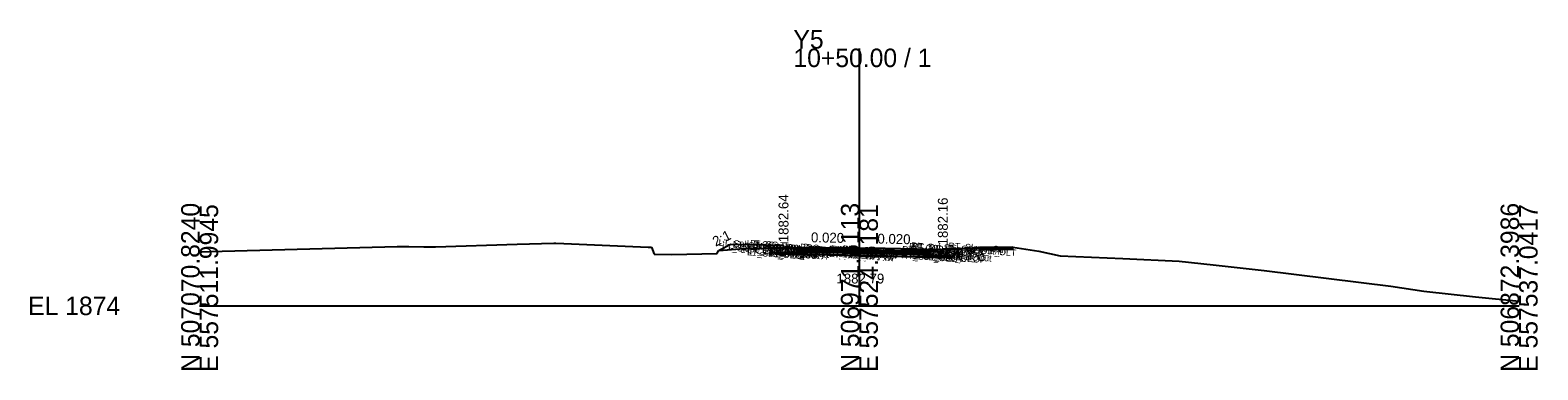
# Model space of a CAD drawing. Extents: x -26 to 1503, y -10 to 2043.
# Drawn here: x -25.7 to 202.8, y 490.3 to 541.8 of the extents above; entities that cross this region are included whole.
import ezdxf

# ---------------------------------------------------------------- set-up
doc = ezdxf.new("R2010")
doc.units = 0
for name, color, linetype in [('Default', 7, 'Continuous'), ('Exist Cross Section Cell', 7, 'Continuous'), ('Exist XS Center Line Elevation Label', 7, 'Continuous'), ('Exist XS Ground Line', 7, 'Continuous'), ('Prop CMT Conc Surface', 7, 'Continuous'), ('Prop CMT Concrete Structures', 7, 'Continuous'), ('Prop CMT Pvmt Course 1', 7, 'Continuous'), ('Prop CMT Pvmt Course 1 CG', 7, 'Continuous'), ('Prop CMT Pvmt Course 2', 7, 'Continuous'), ('Prop CMT Pvmt Course 3', 7, 'Continuous'), ('Prop CMT Pvmt Surface', 7, 'Continuous'), ('Prop CMT Slope Grass', 7, 'Continuous'), ('Prop CMT Subgrade Earthwork', 7, 'Continuous'), ('Prop XS Earthwork Shape', 7, 'Continuous'), ('Prop XS Hydro Elevations', 7, 'Continuous'), ('Prop XS SE Text', 7, 'Continuous'), ('Prop XS Side Slope Text', 7, 'Continuous'), ('Typical Text Asphalt at Bridge Approach CELL', 7, 'Continuous')]:
    doc.layers.add(name, color=color, linetype=linetype)

msp = doc.modelspace()

# ---------------------------------------------------------------- linework, layer by layer
at = {"layer": 'Exist Cross Section Cell'}
for p, q in [((100, 500), (100, 538.98)), ((0, 500), (100, 500)), ((100, 500), (200, 500))]:
    msp.add_line(p, q, dxfattribs=at)
at = {"layer": 'Exist XS Ground Line'}
for p, q in [((0, 508.17), (0.32, 508.19)), ((0.32, 508.19), (1.55, 508.22)), ((1.55, 508.22), (29.94, 508.98)), ((29.94, 508.98), (31.72, 509)), ((31.72, 509), (33.96, 508.97)), ((33.96, 508.97), (35.04, 508.96)), ((35.04, 508.96), (35.77, 508.97)), ((35.77, 508.97), (48.11, 509.35)), ((48.11, 509.35), (53.69, 509.5)), ((53.69, 509.5), (53.99, 509.48)), ((53.99, 509.48), (55.21, 509.43)), ((55.21, 509.43), (67.97, 508.91)), ((67.97, 508.91), (68.49, 508.91)), ((68.49, 508.91), (68.91, 507.84)), ((68.91, 507.84), (71.52, 507.8)), ((71.52, 507.8), (78.43, 507.93)), ((78.43, 507.93), (78.63, 508.4)), ((78.63, 508.4), (81.89, 508.65)), ((81.89, 508.65), (90.53, 508.85)), ((90.53, 508.85), (94.84, 508.82)), ((94.84, 508.82), (99.36, 508.81)), ((99.36, 508.81), (100, 508.79)), ((100, 508.79), (103.93, 508.72)), ((103.93, 508.72), (108.62, 508.64)), ((108.62, 508.64), (113.17, 508.49)), ((113.17, 508.49), (113.63, 508.5)), ((113.63, 508.5), (118.28, 508.87)), ((118.28, 508.87), (120.69, 508.9)), ((120.69, 508.9), (123.26, 508.92)), ((123.26, 508.92), (127.2, 508.27)), ((127.2, 508.27), (130.42, 507.59)), ((130.42, 507.59), (139.92, 507.16)), ((139.92, 507.16), (148.47, 506.76)), ((148.47, 506.76), (153.63, 506.21)), ((153.63, 506.21), (161.37, 505.34)), ((161.37, 505.34), (180.58, 502.98)), ((180.58, 502.98), (185.58, 502.24)), ((185.58, 502.24), (193.37, 501.36)), ((193.37, 501.36), (200, 500.71))]:
    msp.add_line(p, q, dxfattribs=at)
at = {"layer": 'Prop CMT Conc Surface'}
for points in [[(88.5, 508.64), (88.5, 509.14), (88, 509.14)], [(90.5, 508.68), (88.5, 508.64)], [(110.65, 508.28), (112.65, 508.16)], [(112.65, 508.16), (112.65, 508.66), (113.15, 508.66)], [(118.27, 508.81), (123.27, 508.91)]]:
    msp.add_lwpolyline(points, dxfattribs=at)
at = {"layer": 'Prop CMT Concrete Structures'}
for points in [[(90.5, 508.68), (88.5, 508.64), (88.5, 509.14), (88, 509.14)], [(88, 509.14), (88, 508.15), (90.5, 508.1)], [(90.5, 508.1), (90.5, 508.68)], [(110.65, 508.28), (112.65, 508.16), (112.65, 508.66), (113.15, 508.66)], [(113.15, 508.66), (113.15, 507.65), (110.65, 507.7)], [(110.65, 507.7), (110.65, 508.28)], [(123.27, 508.91), (118.27, 508.81)], [(118.27, 508.81), (118.27, 508.48)], [(118.27, 508.48), (123.27, 508.58)], [(123.27, 508.58), (123.27, 508.91)]]:
    msp.add_lwpolyline(points, dxfattribs=at)
at = {"layer": 'Prop CMT Pvmt Course 1'}
for points in [[(100, 508.49), (90.5, 508.68)], [(90.5, 508.68), (90.5, 508.43)], [(90.5, 508.43), (100, 508.24)], [(100, 508.24), (100, 508.49)], [(100, 508.49), (110.65, 508.28)], [(100, 508.24), (100, 508.49)], [(110.65, 508.03), (100, 508.24)], [(110.65, 508.28), (110.65, 508.03)]]:
    msp.add_lwpolyline(points, dxfattribs=at)
msp.add_lwpolyline([(100, 508.24), (100, 508.37), (100, 508.37), (100, 508.24)], close=True, dxfattribs=at)
msp.add_lwpolyline([(100, 508.24), (100, 508.37), (100, 508.37), (100, 508.24)], close=True, dxfattribs=at)
at = {"layer": 'Prop CMT Pvmt Course 1 CG'}
for points in [[(90.5, 508.1), (87.5, 508.16), (87.22, 507.87)], [(87.22, 507.87), (90.5, 507.81)], [(90.5, 507.81), (90.5, 508.1)], [(110.65, 507.7), (113.65, 507.64), (113.95, 507.34)], [(110.65, 507.4), (110.65, 507.7)], [(113.95, 507.34), (110.65, 507.4)]]:
    msp.add_lwpolyline(points, dxfattribs=at)
at = {"layer": 'Prop CMT Pvmt Course 2'}
for points in [[(100, 508.24), (90.5, 508.43)], [(90.5, 508.43), (90.5, 508.18)], [(90.5, 508.18), (100, 507.99)], [(100, 507.99), (100, 508.24)], [(100, 507.99), (100, 508.24)], [(100, 508.24), (110.65, 508.03)], [(110.65, 507.78), (100, 507.99)], [(110.65, 508.03), (110.65, 507.78)]]:
    msp.add_lwpolyline(points, dxfattribs=at)
at = {"layer": 'Prop CMT Pvmt Course 3'}
for points in [[(100, 507.99), (90.5, 508.18)], [(90.5, 508.18), (90.5, 507.81)], [(90.5, 507.81), (100, 507.62)], [(100, 507.62), (100, 507.99)], [(100, 507.99), (110.65, 507.78)], [(100, 507.62), (100, 507.99)], [(110.65, 507.4), (100, 507.62)], [(110.65, 507.78), (110.65, 507.4)]]:
    msp.add_lwpolyline(points, dxfattribs=at)
at = {"layer": 'Prop CMT Pvmt Surface'}
for points in [[(100, 508.49), (90.5, 508.68)], [(100, 508.49), (110.65, 508.28)]]:
    msp.add_lwpolyline(points, dxfattribs=at)
at = {"layer": 'Prop CMT Slope Grass'}
msp.add_line((80.5, 509.29), (78.73, 508.41), dxfattribs=at)
for points in [[(88, 509.14), (80.5, 509.29)], [(113.15, 508.66), (123.34, 508.86), (123.34, 508.91)]]:
    msp.add_lwpolyline(points, dxfattribs=at)
at = {"layer": 'Prop CMT Subgrade Earthwork'}
for points in [[(90.5, 507.81), (87.22, 507.87), (85.91, 509.18)], [(100, 507.62), (90.5, 507.81)], [(100, 507.62), (110.65, 507.4)], [(110.65, 507.4), (113.95, 507.34), (115.31, 508.7)]]:
    msp.add_lwpolyline(points, dxfattribs=at)
at = {"layer": 'Prop XS Earthwork Shape'}
for points in [[(86.34, 508.75), (85.91, 509.18), (80.5, 509.29), (78.73, 508.41), (81.89, 508.65)], [(113.95, 507.34), (115.22, 508.61), (113.63, 508.5), (113.17, 508.49), (112.65, 508.5), (112.65, 508.16), (110.65, 508.28), (100, 508.49), (90.5, 508.68), (88.5, 508.64), (88.5, 508.8), (86.34, 508.75), (87.22, 507.87), (90.5, 507.81), (100, 507.62), (110.65, 507.4)], [(88.5, 508.8), (90.53, 508.85), (94.84, 508.82), (99.36, 508.81), (100, 508.79), (103.93, 508.72), (108.62, 508.64), (112.65, 508.5), (112.65, 508.16), (110.65, 508.28), (100, 508.49), (90.5, 508.68), (88.5, 508.64)], [(115.32, 508.71), (117.69, 508.77), (115.22, 508.61)], [(117.69, 508.77), (123.27, 508.91), (118.27, 508.81)], [(118.27, 508.81), (120.69, 508.9), (123.27, 508.91)]]:
    msp.add_lwpolyline(points, close=True, dxfattribs=at)

# ---------------------------------------------------------------- texts
at = {"layer": 'Default'}
msp.add_text('-', height=0.0001, dxfattribs=at).set_placement((0, 500))
at = {"layer": 'Exist Cross Section Cell'}
for s, p in [('Y5', (90, 538.98)), ('10+50.00 / 1', (90, 536.18)), ('EL 1874', (-26, 498.6))]:
    msp.add_text(s, height=2.8, dxfattribs=at).set_placement(p)
for s, p in [('N 507070.8240', (0, 490)), ('E 557511.9945', (2.8, 490)), ('N 506971.6113', (100, 490)), ('E 557524.5181', (102.8, 490)), ('N 506872.3986', (200, 490)), ('E 557537.0417', (202.8, 490))]:
    msp.add_text(s, height=2.8, rotation=90, dxfattribs=at).set_placement(p)
at = {"layer": 'Exist XS Center Line Elevation Label'}
msp.add_text('1882.79', height=1.5, dxfattribs=at).set_placement((96.52, 503.39))
at = {"layer": 'Prop XS Hydro Elevations'}
for s, p in [('1882.64', (89.25, 509.64)), ('1882.16', (113.4, 509.16))]:
    msp.add_text(s, height=1.5, rotation=90, dxfattribs=at).set_placement(p)
at = {"layer": 'Prop XS SE Text'}
for p in [(92.65, 509.64), (102.72, 509.44)]:
    msp.add_text('0.020', height=1.5, rotation=358.8542, dxfattribs=at).set_placement(p)
at = {"layer": 'Prop XS Side Slope Text'}
msp.add_text('2:1', height=1.5, rotation=26.5651, dxfattribs=at).set_placement((78.21, 508.95))
at = {"layer": 'Typical Text Asphalt at Bridge Approach CELL'}
for s, p in [('LT_Sub_Trench_Out_DLT', (78.62, 509.12)), ('LT_CSLP_Pnt', (80.78, 508.83)), ('LT_CG_Top_BOC', (82.89, 509)), ('LT_CG_Top_Face', (83.4, 509)), ('LT_Slope_Fill', (79.14, 508.44)), ('LT_CG1_Shelf_Out', (81.97, 508.05)), ('LT_Sub_OEOP', (82.96, 507.67)), ('LT_CG_Bot_BOC', (83.03, 508)), ('LT_CG_Top_Gut', (83.67, 508.48)), ('LT_PV2_OEOT', (86.22, 508.23)), ('LT_PV3_OEOT', (86.22, 507.98)), ('LT_Sub_OEOT', (86.25, 507.6)), ('LT_PV1_OEOT', (86.34, 508.47)), ('LT_CG_Bot_IE', (86.4, 507.89)), ('RT_PV2_OEEOP', (95.31, 508.07)), ('RT_PV3_OEEOP', (95.31, 507.82)), ('RT_Sub_OEEOP', (95.33, 507.44)), ('LT_PV2_OEEOP', (95.37, 508.07)), ('LT_PV3_OEEOP', (95.37, 507.82)), ('LT_Sub_OEEOP', (95.39, 507.44)), ('RT_PV1_OEEOP', (95.43, 508.19)), ('LT_PV1_OEEOP', (95.49, 508.18)), ('RT_PV2_IEEOP', (95.69, 508.04)), ('LT_PV2_IEEOP', (95.75, 508.04)), ('RT_PV1_IEEOP', (95.81, 508.16)), ('LT_PV1_IEEOP', (95.87, 508.16)), ('PV2_PGL', (97.32, 507.93)), ('PV1_PGL', (97.44, 508.17)), ('RT_PV2_OEOT', (106.31, 507.83)), ('RT_PV3_OEOT', (106.31, 507.58)), ('RT_Sub_OEOT', (106.34, 507.21)), ('RT_PV1_OEOT', (106.43, 508.07)), ('RT_CG_Bot_IE', (106.49, 507.49)), ('RT_CG_Top_Face', (107.49, 508.52)), ('RT_CG_Top_Gut', (107.75, 508)), ('RT_Sub_Trench_Out_DLT', (107.8, 508.64)), ('RT_CG_Top_BOC', (107.98, 508.52)), ('RT_CG1_Shelf_Out', (108.06, 507.53)), ('RT_CG_Bot_BOC', (108.11, 507.5)), ('RT_Sub_OEOP', (109.63, 507.14)), ('RT_CSLP_Pnt', (112.87, 508.35)), ('RT_Slope_Cut', (113.48, 508.6))]:
    msp.add_text(s, height=1, rotation=356, dxfattribs=at).set_placement(p)

doc.saveas('drawing.dxf')
